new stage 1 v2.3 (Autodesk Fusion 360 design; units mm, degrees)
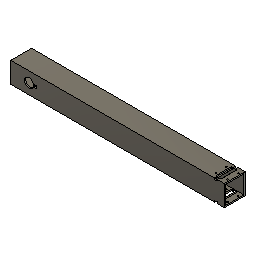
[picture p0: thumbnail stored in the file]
parameter "d495" = 0
parameter "d496" = 0
parameter "d497" = 0
parameter "d498" = 0
sketch "Sketch1" plane through (0, 0, 0) normal (1, 0, 0) x axis (0, 0, -1)
  line L1 (50.8, 0) -> (0, 0)
  line L2 (50.8, 50.8) -> (50.8, 0)
  line L3 (0, 50.8) -> (50.8, 50.8)
  line L4 (0, 0) -> (0, 50.8)
  line L5 (47.5234, 3.2766) -> (3.2766, 3.2766)
  line L6 (47.5234, 47.5234) -> (47.5234, 3.2766)
  line L7 (3.2766, 47.5234) -> (47.5234, 47.5234)
  line L8 (3.2766, 3.2766) -> (3.2766, 47.5234)
  point P1 (0, 0)
  point P2 (0, 0)
  point P3 (50.8, 0)
  point P5 (0, 50.8)
  horizontal L1
  vertical L2
  horizontal L3
  vertical L4
  coincident P1 P2
  dimension "d1_1" distance P2 P3 = 50.8
  dimension "d2_1" distance P2 P5 = 50.8
  dimension "d3_1" = -3.2766
  dimension "d158" OffsetX = 0
  dimension "d159" OffsetY = 0
  dimension "d160" OffsetZ = 0
  dimension "d161" AngleZ = 0
  dimension "d215" OffsetX = 0
  dimension "d216" OffsetY = 0
  dimension "d217" OffsetZ = 0
  dimension "d218" AngleZ = 0
  dimension "d223" OffsetX = 0
  dimension "d224" OffsetY = 0
  dimension "d225" OffsetZ = 0
  dimension "d226" AngleZ = 0
  dimension "d231" OffsetX = 0
  dimension "d232" OffsetY = 0
  dimension "d233" OffsetZ = 0
  dimension "d234" AngleZ = 0
  dimension "d239" OffsetX = 0
  dimension "d240" OffsetY = 0
  dimension "d241" OffsetZ = 0
  dimension "d242" AngleZ = 0
  dimension "d339" OffsetX = 0
  dimension "d340" OffsetY = 0
  dimension "d341" OffsetZ = 0
  dimension "d342" AngleZ = 0
  dimension "d347" OffsetX = 0
  dimension "d348" OffsetY = 0
  dimension "d349" OffsetZ = 0
  dimension "d350" AngleZ = 0
  dimension "d355" OffsetX = 0
  dimension "d356" OffsetY = 0
  dimension "d357" OffsetZ = 0
  dimension "d358" AngleZ = 0
  dimension "d363" OffsetX = 0
  dimension "d364" OffsetY = 0
  dimension "d365" OffsetZ = 0
  dimension "d366" AngleZ = 0
  dimension "d376" OffsetX = 0
  dimension "d377" OffsetY = 0
  dimension "d378" OffsetZ = 0
  dimension "d379" AngleZ = 0
  dimension "d384" OffsetX = 0
  dimension "d385" OffsetY = 0
  dimension "d386" OffsetZ = 0
  dimension "d387" AngleZ = 0
  dimension "d392" OffsetX = 0
  dimension "d393" OffsetY = 0
  dimension "d394" OffsetZ = 0
  dimension "d395" AngleZ = 0
  dimension "d479" OffsetX = 0
  dimension "d480" OffsetY = 0
  dimension "d481" OffsetZ = 0
  dimension "d482" AngleZ = 0
  dimension "d487" OffsetX = 0
  dimension "d488" OffsetY = 0
  dimension "d489" OffsetZ = 0
  dimension "d490" AngleZ = 0
extrude "Extrude1" new body sketch "Sketch1" along a picked direction blind 520.7 named "d4_1"
hole "Hole2" HoleDepth 101.6 HoleDiameter 22.225 TipAngle 118 RefDim1 44.45 (= "1 in + ( 3 / 4 ) * 1 in") RefDim2 25.4
sketch "Sketch2" plane through (0, 0, 0) normal (0, 0, 1) x axis (1, 0, 0)
  line L1 (0, 50.8) -> (520.7, 50.8)
  line L2 (0, 0) -> (0, 50.8)
  line L3 (520.7, 0) -> (0, 0)
  line L4 (496.7478, 47.498) -> (503.3518, 47.498)
  line L5 (496.7478, 54.102) -> (496.7478, 47.498)
  line L6 (503.3518, 54.102) -> (496.7478, 54.102)
  line L7 (503.3518, 47.498) -> (503.3518, 54.102)
  line L8 (496.7478, 54.102) -> (503.3518, 47.498)
  line L9 (503.3518, 54.102) -> (496.7478, 47.498)
  line L10 (496.7478, 3.302) -> (503.3518, 3.302)
  line L11 (496.7478, -3.302) -> (496.7478, 3.302)
  line L12 (503.3518, -3.302) -> (496.7478, -3.302)
  line L13 (503.3518, 3.302) -> (503.3518, -3.302)
  line L14 (496.7478, -3.302) -> (503.3518, 3.302)
  line L15 (503.3518, -3.302) -> (496.7478, 3.302)
  line L16 (520.7, 50.8) -> (520.7, 0)
  line L17 (520.7, 50.8) -> (520.7, 0)
  circle C1 centre (44.45, 25.4) radius 11.1125
  circle C2 centre (500.0498, 50.8) radius 3.302
  circle C3 centre (500.0498, 0) radius 3.302
  point P7 (500.0498, 50.8)
  point P8 (500.0498, 0)
  point P13 (500.0498, 50.8)
  point P18 (500.0498, 0)
  point P10 (496.7478, 47.498)
  point P11 (496.7478, 54.102)
  point P12 (503.3518, 54.102)
  point P16 (496.7478, -3.302)
  point P17 (503.3518, -3.302)
  point P15 (496.7478, 3.302)
  coincident L1 P7
  coincident L3 P8
  perpendicular L4 L5
  parallel L4 L6
  parallel L5 L7
  horizontal L4
  coincident L8 P13
  coincident L9 P13
  coincident P7 P13
  perpendicular L10 L11
  parallel L10 L12
  parallel L11 L13
  horizontal L10
  coincident L14 P18
  coincident L15 P18
  coincident P8 P18
  dimension "d412" diameter C2 = 6.604
  dimension "d413" diameter C3 = 6.604
  dimension "d428" distance P10 P11 = 6.604
  dimension "d429" distance P11 P12 = 6.604
  dimension "d430" distance P16 P17 = 6.604
  dimension "d431" distance P15 P16 = 6.604
  dimension "d540" distance L13 L17 = 17.3482
  dimension "d541" distance L7 L17 = 17.3482
extrude "Extrude3" cut sketch "Sketch2" profile of L1 L3 C2 C3 L4 L5 L7 L10 L11 L13 along a picked direction blind -50.8
sketch "Sketch3" plane through (0, 0, 0) normal (0, -1, 0) x axis (1, 0, 0)
  line L1 (520.7, -50.8) -> (503.3518, -50.8)
  line L2 (503.3518, 0) -> (520.7, 0)
  line L3 (493.1918, -6.35) -> (506.9078, -6.35)
  line L4 (493.1918, -19.05) -> (493.1918, -6.35)
  line L5 (506.9078, -19.05) -> (493.1918, -19.05)
  line L6 (506.9078, -6.35) -> (506.9078, -19.05)
  line L7 (493.1918, -19.05) -> (506.9078, -19.05)
  line L8 (493.1918, -44.45) -> (493.1918, -19.05)
  line L9 (506.9078, -44.45) -> (493.1918, -44.45)
  line L10 (506.9078, -19.05) -> (506.9078, -44.45)
  line L11 (503.3518, -50.8) -> (503.3518, 0)
  line L12 (496.7478, 0) -> (496.7478, -50.8)
  line L13 (520.7, 0) -> (520.7, -50.8)
  line L14 (496.7478, 0) -> (496.7478, -50.8)
  line L15 (0, 0) -> (496.7478, 0)
  line L16 (0, -50.8) -> (0, 0)
  line L17 (496.7478, -50.8) -> (0, -50.8)
  point P6 (506.9078, -6.35)
  point P9 (506.9078, -19.05)
  point P7 (493.1918, -6.35)
  point P10 (506.9078, -19.05)
  point P11 (493.1918, -19.05)
  point P13 (506.9078, -44.45)
  horizontal L3
  vertical L4
  horizontal L5
  vertical L6
  horizontal L7
  vertical L8
  horizontal L9
  vertical L10
  dimension "d418" distance P6 P9 = 12.7
  dimension "d419" distance P6 P7 = 13.716
  dimension "d420" distance P10 P11 = 13.716
  dimension "d421" distance P10 P13 = 25.4
  dimension "d422" distance L1 L9 = 6.35
  dimension "d423" distance L2 L3 = 6.35
  dimension "d432" distance L4 L12 = 3.556
  dimension "d433" distance L8 L12 = 3.556
extrude "Extrude4" cut sketch "Sketch3" profile of L3 L4 L5 L6 L7 L8 L9 L10 L11 L12 against normal blind 3.175
extrude "Extrude5" sketch "Sketch3" profile of L3 L4 L5 L6 L7 L8 L9 L10 L11 L12 blind 3.175
fillet "Fillet1" radius 1.5875 1.5875
sketch "Sketch4" plane through (0, 50.8, 0) normal (0, 1, 0) x axis (-1, 0, 0)
  line L1 (-469.3793, -6.35) -> (-469.7603, -6.35)
  line L2 (-467.7918, -42.8625) -> (-467.7918, -7.9375)
  line L3 (-469.7603, -44.45) -> (-469.3793, -44.45)
  line L4 (-471.3478, -50.8) -> (-471.3478, -46.0375)
  line L5 (0, -50.8) -> (-471.3478, -50.8)
  line L6 (0, 0) -> (0, -50.8)
  line L7 (-471.3478, 0) -> (0, 0)
  line L8 (-471.3478, -4.7625) -> (-471.3478, 0)
  line L9 (-520.7, -50.8) -> (-477.9518, -50.8)
  line L10 (-503.3518, 0) -> (-503.3518, -4.7625)
  line L11 (-520.7, 0) -> (-503.3518, 0)
  line L12 (-520.7, -50.8) -> (-520.7, 0)
  line L13 (-503.3518, -50.8) -> (-520.7, -50.8)
  line L14 (-503.3518, -46.0375) -> (-503.3518, -50.8)
  line L15 (-505.3203, -44.45) -> (-504.9393, -44.45)
  line L16 (-506.9078, -7.9375) -> (-506.9078, -42.8625)
  line L17 (-504.9393, -6.35) -> (-505.3203, -6.35)
  arc A1 centre (-469.7603, -4.7625) radius 1.5875 clockwise from (-469.7603, -6.35) to (-471.3478, -4.7625)
  arc A2 centre (-469.3793, -7.9375) radius 1.5875 clockwise from (-469.3793, -6.35) to (-467.7918, -7.9375)
  arc A3 centre (-469.7603, -46.0375) radius 1.5875 clockwise from (-471.3478, -46.0375) to (-469.7603, -44.45)
  circle C1 centre (-515.9248, -38.1) radius 2.5527
  circle C2 centre (-487.3498, -38.1) radius 2.5527
  circle C3 centre (-515.9248, -12.7) radius 2.5527
  circle C4 centre (-487.3498, -12.7) radius 2.5527
  arc A4 centre (-469.3793, -42.8625) radius 1.5875 clockwise from (-467.7918, -42.8625) to (-469.3793, -44.45)
  arc A5 centre (-504.9393, -4.7625) radius 1.5875 clockwise from (-503.3518, -4.7625) to (-504.9393, -6.35)
  arc A6 centre (-504.9393, -46.0375) radius 1.5875 clockwise from (-504.9393, -44.45) to (-503.3518, -46.0375)
  arc A7 centre (-505.3203, -42.8625) radius 1.5875 clockwise from (-505.3203, -44.45) to (-506.9078, -42.8625)
  arc A8 centre (-505.3203, -7.9375) radius 1.5875 clockwise from (-506.9078, -7.9375) to (-505.3203, -6.35)
  point P17 (-515.9248, -38.1)
  dimension "d441" diameter C1 = 5.1054
  dimension "d443" distance P17 L9 = 12.7
  dimension "d539" distance P17 L12 = 4.7752
  dimension "d446" R-Pattern1-uDistance = 28.575
  dimension "d447" R-Pattern1-vDistance = 25.4
hole "Hole3" HoleDepth 50.8 HoleDiameter 3.429 TipAngle 118
sketch "Sketch5" plane through (0, 0, 0) normal (0, 0, 1) x axis (1, 0, 0)
  line L1 (503.3518, 47.498) -> (503.3518, 50.8)
  line L2 (496.7478, 47.498) -> (503.3518, 47.498)
  line L3 (496.7478, 50.8) -> (496.7478, 47.498)
  line L4 (0, 50.8) -> (496.7478, 50.8)
  line L5 (0, 0) -> (0, 50.8)
  line L6 (496.7478, 0) -> (0, 0)
  line L7 (496.7478, 3.302) -> (496.7478, 0)
  line L8 (503.3518, 3.302) -> (496.7478, 3.302)
  line L9 (503.3518, 0) -> (503.3518, 3.302)
  line L10 (520.7, 0) -> (503.3518, 0)
  line L11 (520.7, 50.8) -> (520.7, 0)
  line L12 (503.3518, 50.8) -> (520.7, 50.8)
  circle C1 centre (44.45, 25.4) radius 11.1125
  circle C2 centre (60.325, 25.4) radius 3.3782
  point P14 (44.45, 25.4)
  point P15 (60.325, 25.4)
  dimension "d542" diameter C2 = 6.7564
  dimension "d543" distance P14 P15 = 15.875
  dimension "d544" distance L4 P15 = 25.4
hole "Hole4" HoleDepth 38.1 HoleDiameter 6.7564 TipAngle 118
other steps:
thread "Thread1"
